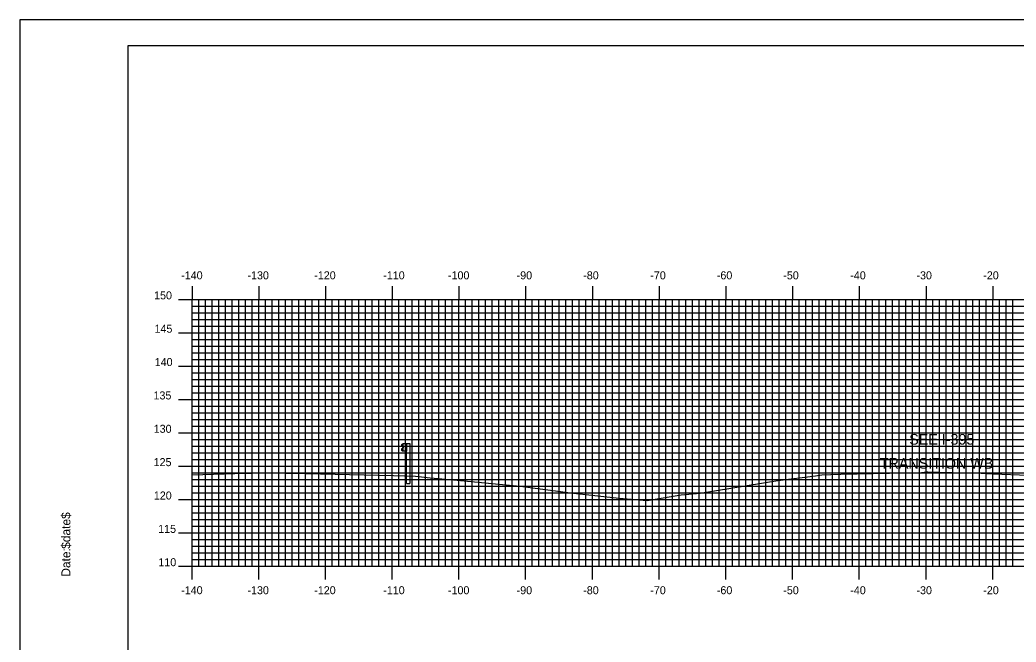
# Model space of a CAD drawing. Extents: x 853721 to 854064, y 364661 to 364881.
# Drawn here: x 853721 to 853870.3, y 364788 to 364881.3 of the extents above; entities that cross this region are included whole.
import ezdxf

# ---------------------------------------------------------------- set-up
doc = ezdxf.new("R2010")
doc.units = 0
for name, color, linetype in [('ANNOTATION', 7, 'Continuous'), ('BORDER', 7, 'Continuous'), ('H_V ANNOTATION', 7, 'Continuous'), ('M_Guardrail', 7, 'Continuous'), ('M_Roadway_Centerline', 7, 'Continuous'), ('MAJOR', 7, 'Continuous'), ('MINOR', 7, 'Continuous'), ('PLOT BOUNDARY', 7, 'Continuous'), ('S_Roadway_Centerline', 7, 'Continuous')]:
    doc.layers.add(name, color=color, linetype=linetype)

msp = doc.modelspace()

# ---------------------------------------------------------------- linework, layer by layer
at = {"layer": 'BORDER'}
msp.add_lwpolyline([(853737.21, 364667.37), (854057.21, 364667.37), (854057.21, 364877.37), (853737.21, 364877.37)], close=True, dxfattribs=at)
at = {"layer": 'M_Guardrail'}
for p, q in [((853778.37, 364817.66), (853778.23, 364817.56)), ((853778.23, 364817.41), (853778.42, 364817.28)), ((853778.42, 364817.06), (853778.23, 364816.92)), ((853778.23, 364816.78), (853778.37, 364816.68)), ((853778.47, 364817.68), (853778.39, 364817.66)), ((853778.39, 364816.67), (853778.47, 364816.66)), ((853778.46, 364817.21), (853778.46, 364817.12)), ((853778.47, 364817.75), (853778.96, 364817.75)), ((853778.47, 364816.59), (853778.47, 364817.75)), ((853778.96, 364816.59), (853778.47, 364816.59)), ((853778.96, 364817.75), (853779.45, 364817.75)), ((853778.96, 364817.75), (853778.96, 364816.59)), ((853778.96, 364811.75), (853778.96, 364816.59)), ((853779.45, 364817.75), (853779.45, 364811.75)), ((853778.96, 364811.75), (853779.45, 364811.75))]:
    msp.add_line(p, q, dxfattribs=at)
for centre, major_axis, start_param, end_param in [((853778.28, 364817.49), (-0.0877, 0), 5.323254, 7.243116), ((853778.28, 364816.85), (-0.0877, 0), 5.323254, 7.243116), ((853778.39, 364817.62), (-0.0417, 0), 4.886922, 5.323254), ((853778.39, 364816.71), (-0.0417, 0), 0.959931, 1.396263), ((853778.38, 364817.21), (0.0789, 0), 0, 0.959931), ((853778.38, 364817.12), (0.0789, 0), 5.323254, 6.283185)]:
    msp.add_ellipse(centre, major_axis=major_axis, ratio=0.995501, start_param=start_param, end_param=end_param, dxfattribs=at)
at = {"layer": 'MAJOR'}
for p, q in [((853746.81, 364841.37), (853746.81, 364839.37)), ((853756.81, 364841.37), (853756.81, 364839.37)), ((853766.81, 364841.37), (853766.81, 364839.37)), ((853776.81, 364841.37), (853776.81, 364839.37)), ((853786.81, 364841.37), (853786.81, 364839.37)), ((853796.81, 364841.37), (853796.81, 364839.37)), ((853806.81, 364841.37), (853806.81, 364839.37)), ((853816.81, 364841.37), (853816.81, 364839.37)), ((853826.81, 364841.37), (853826.81, 364839.37)), ((853836.81, 364841.37), (853836.81, 364839.37)), ((853846.81, 364841.37), (853846.81, 364839.37)), ((853856.81, 364841.37), (853856.81, 364839.37)), ((853866.81, 364841.37), (853866.81, 364839.37)), ((853744.8, 364839.37), (853746.81, 364839.37)), ((853746.81, 364839.37), (854026.81, 364839.37)), ((853746.81, 364799.37), (853746.81, 364839.37)), ((853746.81, 364799.37), (853746.81, 364839.37)), ((853746.81, 364839.37), (854026.81, 364839.37)), ((853756.81, 364799.37), (853756.81, 364839.37)), ((853766.81, 364799.37), (853766.81, 364839.37)), ((853776.81, 364799.37), (853776.81, 364839.37)), ((853786.81, 364799.37), (853786.81, 364839.37)), ((853796.81, 364799.37), (853796.81, 364839.37)), ((853806.81, 364799.37), (853806.81, 364839.37)), ((853816.81, 364799.37), (853816.81, 364839.37)), ((853826.81, 364799.37), (853826.81, 364839.37)), ((853836.81, 364799.37), (853836.81, 364839.37)), ((853846.81, 364799.37), (853846.81, 364839.37)), ((853856.81, 364799.37), (853856.81, 364839.37)), ((853866.81, 364799.37), (853866.81, 364839.37)), ((853744.8, 364834.37), (853746.81, 364834.37)), ((853746.81, 364834.37), (854026.81, 364834.37)), ((853744.8, 364829.37), (853746.81, 364829.37)), ((853746.81, 364829.37), (854026.81, 364829.37)), ((853744.8, 364824.37), (853746.81, 364824.37)), ((853746.81, 364824.37), (854026.81, 364824.37)), ((853744.8, 364819.37), (853746.81, 364819.37)), ((853746.81, 364819.37), (854026.81, 364819.37)), ((853744.8, 364814.37), (853746.81, 364814.37)), ((853746.81, 364814.37), (854026.81, 364814.37)), ((853744.8, 364809.37), (853746.81, 364809.37)), ((853746.81, 364809.37), (854026.81, 364809.37)), ((853744.8, 364804.37), (853746.81, 364804.37)), ((853746.81, 364804.37), (854026.81, 364804.37)), ((853744.8, 364799.37), (853746.81, 364799.37)), ((853746.81, 364799.37), (854026.81, 364799.37)), ((853746.81, 364799.37), (854026.81, 364799.37)), ((853746.81, 364797.37), (853746.81, 364799.37)), ((853756.81, 364797.37), (853756.81, 364799.37)), ((853766.81, 364797.37), (853766.81, 364799.37)), ((853776.81, 364797.37), (853776.81, 364799.37)), ((853786.81, 364797.37), (853786.81, 364799.37)), ((853796.81, 364797.37), (853796.81, 364799.37)), ((853806.81, 364797.37), (853806.81, 364799.37)), ((853816.81, 364797.37), (853816.81, 364799.37)), ((853826.81, 364797.37), (853826.81, 364799.37)), ((853836.81, 364797.37), (853836.81, 364799.37)), ((853846.81, 364797.37), (853846.81, 364799.37)), ((853856.81, 364797.37), (853856.81, 364799.37)), ((853866.81, 364797.37), (853866.81, 364799.37))]:
    msp.add_line(p, q, dxfattribs=at)
at = {"layer": 'MINOR'}
for p, q in [((853747.81, 364799.37), (853747.81, 364839.37)), ((853748.81, 364799.37), (853748.81, 364839.37)), ((853749.81, 364799.37), (853749.81, 364839.37)), ((853750.81, 364799.37), (853750.81, 364839.37)), ((853751.81, 364799.37), (853751.81, 364839.37)), ((853752.81, 364799.37), (853752.81, 364839.37)), ((853753.81, 364799.37), (853753.81, 364839.37)), ((853754.81, 364799.37), (853754.81, 364839.37)), ((853755.81, 364799.37), (853755.81, 364839.37)), ((853757.81, 364799.37), (853757.81, 364839.37)), ((853758.81, 364799.37), (853758.81, 364839.37)), ((853759.81, 364799.37), (853759.81, 364839.37)), ((853760.81, 364799.37), (853760.81, 364839.37)), ((853761.81, 364799.37), (853761.81, 364839.37)), ((853762.81, 364799.37), (853762.81, 364839.37)), ((853763.81, 364799.37), (853763.81, 364839.37)), ((853764.81, 364799.37), (853764.81, 364839.37)), ((853765.81, 364799.37), (853765.81, 364839.37)), ((853767.81, 364799.37), (853767.81, 364839.37)), ((853768.81, 364799.37), (853768.81, 364839.37)), ((853769.81, 364799.37), (853769.81, 364839.37)), ((853770.81, 364799.37), (853770.81, 364839.37)), ((853771.81, 364799.37), (853771.81, 364839.37)), ((853772.81, 364799.37), (853772.81, 364839.37)), ((853773.81, 364799.37), (853773.81, 364839.37)), ((853774.81, 364799.37), (853774.81, 364839.37)), ((853775.81, 364799.37), (853775.81, 364839.37)), ((853777.81, 364799.37), (853777.81, 364839.37)), ((853778.81, 364799.37), (853778.81, 364839.37)), ((853779.81, 364799.37), (853779.81, 364839.37)), ((853780.81, 364799.37), (853780.81, 364839.37)), ((853781.81, 364799.37), (853781.81, 364839.37)), ((853782.81, 364799.37), (853782.81, 364839.37)), ((853783.81, 364799.37), (853783.81, 364839.37)), ((853784.81, 364799.37), (853784.81, 364839.37)), ((853785.81, 364799.37), (853785.81, 364839.37)), ((853787.81, 364799.37), (853787.81, 364839.37)), ((853788.81, 364799.37), (853788.81, 364839.37)), ((853789.81, 364799.37), (853789.81, 364839.37)), ((853790.81, 364799.37), (853790.81, 364839.37)), ((853791.81, 364799.37), (853791.81, 364839.37)), ((853792.81, 364799.37), (853792.81, 364839.37)), ((853793.81, 364799.37), (853793.81, 364839.37)), ((853794.81, 364799.37), (853794.81, 364839.37)), ((853795.81, 364799.37), (853795.81, 364839.37)), ((853797.81, 364799.37), (853797.81, 364839.37)), ((853798.81, 364799.37), (853798.81, 364839.37)), ((853799.81, 364799.37), (853799.81, 364839.37)), ((853800.81, 364799.37), (853800.81, 364839.37)), ((853801.81, 364799.37), (853801.81, 364839.37)), ((853802.81, 364799.37), (853802.81, 364839.37)), ((853803.81, 364799.37), (853803.81, 364839.37)), ((853804.81, 364799.37), (853804.81, 364839.37)), ((853805.81, 364799.37), (853805.81, 364839.37)), ((853807.81, 364799.37), (853807.81, 364839.37)), ((853808.81, 364799.37), (853808.81, 364839.37)), ((853809.81, 364799.37), (853809.81, 364839.37)), ((853810.81, 364799.37), (853810.81, 364839.37)), ((853811.81, 364799.37), (853811.81, 364839.37)), ((853812.81, 364799.37), (853812.81, 364839.37)), ((853813.81, 364799.37), (853813.81, 364839.37)), ((853814.81, 364799.37), (853814.81, 364839.37)), ((853815.81, 364799.37), (853815.81, 364839.37)), ((853817.81, 364799.37), (853817.81, 364839.37)), ((853818.81, 364799.37), (853818.81, 364839.37)), ((853819.81, 364799.37), (853819.81, 364839.37)), ((853820.81, 364799.37), (853820.81, 364839.37)), ((853821.81, 364799.37), (853821.81, 364839.37)), ((853822.81, 364799.37), (853822.81, 364839.37)), ((853823.81, 364799.37), (853823.81, 364839.37)), ((853824.81, 364799.37), (853824.81, 364839.37)), ((853825.81, 364799.37), (853825.81, 364839.37)), ((853827.81, 364799.37), (853827.81, 364839.37)), ((853828.81, 364799.37), (853828.81, 364839.37)), ((853829.81, 364799.37), (853829.81, 364839.37)), ((853830.81, 364799.37), (853830.81, 364839.37)), ((853831.81, 364799.37), (853831.81, 364839.37)), ((853832.81, 364799.37), (853832.81, 364839.37)), ((853833.81, 364799.37), (853833.81, 364839.37)), ((853834.81, 364799.37), (853834.81, 364839.37)), ((853835.81, 364799.37), (853835.81, 364839.37)), ((853837.81, 364799.37), (853837.81, 364839.37)), ((853838.81, 364799.37), (853838.81, 364839.37)), ((853839.81, 364799.37), (853839.81, 364839.37)), ((853840.81, 364799.37), (853840.81, 364839.37)), ((853841.81, 364799.37), (853841.81, 364839.37)), ((853842.81, 364799.37), (853842.81, 364839.37)), ((853843.81, 364799.37), (853843.81, 364839.37)), ((853844.81, 364799.37), (853844.81, 364839.37)), ((853845.81, 364799.37), (853845.81, 364839.37)), ((853847.81, 364799.37), (853847.81, 364839.37)), ((853848.81, 364799.37), (853848.81, 364839.37)), ((853849.81, 364799.37), (853849.81, 364839.37)), ((853850.81, 364799.37), (853850.81, 364839.37)), ((853851.81, 364799.37), (853851.81, 364839.37)), ((853852.81, 364799.37), (853852.81, 364839.37)), ((853853.81, 364799.37), (853853.81, 364839.37)), ((853854.81, 364799.37), (853854.81, 364839.37)), ((853855.81, 364799.37), (853855.81, 364839.37)), ((853857.81, 364799.37), (853857.81, 364839.37)), ((853858.81, 364799.37), (853858.81, 364839.37)), ((853859.81, 364799.37), (853859.81, 364839.37)), ((853860.81, 364799.37), (853860.81, 364839.37)), ((853861.81, 364799.37), (853861.81, 364839.37)), ((853862.81, 364799.37), (853862.81, 364839.37)), ((853863.81, 364799.37), (853863.81, 364839.37)), ((853864.81, 364799.37), (853864.81, 364839.37)), ((853865.81, 364799.37), (853865.81, 364839.37)), ((853867.81, 364799.37), (853867.81, 364839.37)), ((853868.81, 364799.37), (853868.81, 364839.37)), ((853869.81, 364799.37), (853869.81, 364839.37)), ((853746.81, 364838.37), (854026.81, 364838.37)), ((853746.81, 364838.37), (853748.81, 364838.37)), ((853746.81, 364837.37), (854026.81, 364837.37)), ((853746.81, 364837.37), (853748.81, 364837.37)), ((853746.81, 364836.37), (854026.81, 364836.37)), ((853746.81, 364836.37), (853748.81, 364836.37)), ((853746.81, 364835.37), (854026.81, 364835.37)), ((853746.81, 364835.37), (853748.81, 364835.37)), ((853746.81, 364833.37), (854026.81, 364833.37)), ((853746.81, 364833.37), (853748.81, 364833.37)), ((853746.81, 364832.37), (854026.81, 364832.37)), ((853746.81, 364832.37), (853748.81, 364832.37)), ((853746.81, 364831.37), (854026.81, 364831.37)), ((853746.81, 364831.37), (853748.81, 364831.37)), ((853746.81, 364830.37), (854026.81, 364830.37)), ((853746.81, 364830.37), (853748.81, 364830.37)), ((853746.81, 364828.37), (854026.81, 364828.37)), ((853746.81, 364828.37), (853748.81, 364828.37)), ((853746.81, 364827.37), (854026.81, 364827.37)), ((853746.81, 364827.37), (853748.81, 364827.37)), ((853746.81, 364826.37), (854026.81, 364826.37)), ((853746.81, 364826.37), (853748.81, 364826.37)), ((853746.81, 364825.37), (854026.81, 364825.37)), ((853746.81, 364825.37), (853748.81, 364825.37)), ((853746.81, 364823.37), (854026.81, 364823.37)), ((853746.81, 364823.37), (853748.81, 364823.37)), ((853746.81, 364822.37), (854026.81, 364822.37)), ((853746.81, 364822.37), (853748.81, 364822.37)), ((853746.81, 364821.37), (854026.81, 364821.37)), ((853746.81, 364821.37), (853748.81, 364821.37)), ((853746.81, 364820.37), (854026.81, 364820.37)), ((853746.81, 364820.37), (853748.81, 364820.37)), ((853746.81, 364818.37), (854026.81, 364818.37)), ((853746.81, 364818.37), (853748.81, 364818.37)), ((853746.81, 364817.37), (854026.81, 364817.37)), ((853746.81, 364817.37), (853748.81, 364817.37)), ((853746.81, 364816.37), (854026.81, 364816.37)), ((853746.81, 364816.37), (853748.81, 364816.37)), ((853746.81, 364815.37), (854026.81, 364815.37)), ((853746.81, 364815.37), (853748.81, 364815.37)), ((853746.81, 364813.37), (854026.81, 364813.37)), ((853746.81, 364813.37), (853748.81, 364813.37)), ((853746.81, 364812.37), (854026.81, 364812.37)), ((853746.81, 364812.37), (853748.81, 364812.37)), ((853746.81, 364811.37), (854026.81, 364811.37)), ((853746.81, 364811.37), (853748.81, 364811.37)), ((853746.81, 364810.37), (854026.81, 364810.37)), ((853746.81, 364810.37), (853748.81, 364810.37)), ((853746.81, 364808.37), (854026.81, 364808.37)), ((853746.81, 364808.37), (853748.81, 364808.37)), ((853746.81, 364807.37), (854026.81, 364807.37)), ((853746.81, 364807.37), (853748.81, 364807.37)), ((853746.81, 364806.37), (854026.81, 364806.37)), ((853746.81, 364806.37), (853748.81, 364806.37)), ((853746.81, 364805.37), (854026.81, 364805.37)), ((853746.81, 364805.37), (853748.81, 364805.37)), ((853746.81, 364803.37), (854026.81, 364803.37)), ((853746.81, 364803.37), (853748.81, 364803.37)), ((853746.81, 364802.37), (854026.81, 364802.37)), ((853746.81, 364802.37), (853748.81, 364802.37)), ((853746.81, 364801.37), (854026.81, 364801.37)), ((853746.81, 364801.37), (853748.81, 364801.37)), ((853746.81, 364800.37), (854026.81, 364800.37)), ((853746.81, 364800.37), (853748.81, 364800.37))]:
    msp.add_line(p, q, dxfattribs=at)
at = {"layer": 'PLOT BOUNDARY'}
msp.add_lwpolyline([(853721.02, 364661.25), (854061.02, 364661.25), (854061.02, 364881.25), (853721.02, 364881.25)], close=True, dxfattribs=at)
at = {"layer": 'S_Roadway_Centerline'}
msp.add_lwpolyline([(853746.81, 364813.07), (853753.21, 364813.28), (853758.48, 364813.38), (853759.85, 364813.41), (853760.77, 364813.34), (853761.67, 364813.32), (853777.01, 364812.97), (853780.29, 364812.85), (853782.48, 364812.64), (853785.98, 364812.3), (853796.01, 364811.36), (853803.55, 364810.35), (853810.81, 364809.58), (853815, 364809.23), (853815.04, 364809.23), (853820.12, 364810.07), (853822.98, 364810.33), (853834.58, 364812.23), (853840.25, 364812.93), (853841.21, 364813.06), (853842.56, 364813.11), (853844.06, 364813.15), (853853.8, 364813.37), (853856.12, 364813.41), (853856.87, 364813.51), (853857.07, 364813.51), (853858.73, 364813.46), (853865.07, 364813.3), (853865.73, 364813.28), (853866.84, 364813.23), (853877.5, 364812.82)], dxfattribs=at)

# ---------------------------------------------------------------- texts
at = {"layer": 'ANNOTATION'}
for s, p in [('SEE I-395 ', (853854.3, 364817.59)), ('TRANSITION WB', (853849.89, 364813.99))]:
    msp.add_text(s, height=1.6, dxfattribs=at).set_placement(p)
at = {"layer": 'BORDER'}
for s, p in [('$date$', (853728.58, 364801.98)), ('Date:', (853728.58, 364797.8))]:
    msp.add_text(s, height=1.339, rotation=90, dxfattribs=at).set_placement(p)
at = {"layer": 'H_V ANNOTATION'}
for s, p in [('-140', (853745.19, 364842.37)), ('-130', (853755.12, 364842.37)), ('-120', (853765.13, 364842.37)), ('-110', (853775.47, 364842.37)), ('-100', (853785.17, 364842.37)), ('-90', (853795.46, 364842.37)), ('-80', (853805.44, 364842.37)), ('-70', (853815.49, 364842.37)), ('-60', (853825.46, 364842.37)), ('-50', (853835.42, 364842.37)), ('-40', (853845.46, 364842.37)), ('-30', (853855.38, 364842.37)), ('-20', (853865.39, 364842.37)), ('150', (853741.13, 364839.37)), ('145', (853741.19, 364834.37)), ('140', (853741.22, 364829.37)), ('135', (853741.04, 364824.37)), ('130', (853741.07, 364819.37)), ('125', (853741.06, 364814.37)), ('120', (853741.09, 364809.37)), ('115', (853741.74, 364804.37)), ('110', (853741.77, 364799.37)), ('-140', (853745.19, 364795.17)), ('-130', (853755.12, 364795.17)), ('-120', (853765.13, 364795.17)), ('-110', (853775.47, 364795.17)), ('-100', (853785.17, 364795.17)), ('-90', (853795.46, 364795.17)), ('-80', (853805.44, 364795.17)), ('-70', (853815.49, 364795.17)), ('-60', (853825.46, 364795.17)), ('-50', (853835.42, 364795.17)), ('-40', (853845.46, 364795.17)), ('-30', (853855.38, 364795.17)), ('-20', (853865.39, 364795.17))]:
    msp.add_text(s, height=1.2, dxfattribs=at).set_placement(p)
at = {"layer": 'M_Roadway_Centerline'}
for s, p in [('C', (853759.84, 364813.41)), ('L', (853759.85, 364813.4)), ('C', (853857.07, 364813.51)), ('L', (853857.07, 364813.51))]:
    msp.add_text(s, height=0.0146, dxfattribs=at).set_placement(p)
at = {"layer": 'MAJOR'}
msp.add_text('-', height=0.012, dxfattribs=at).set_placement((853746.8, 364799.37))

doc.saveas('drawing.dxf')
